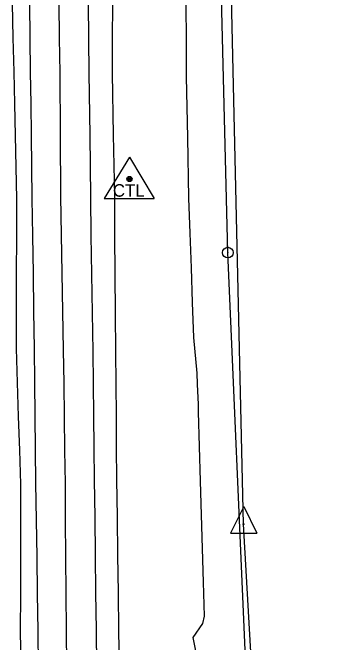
# Model space of a CAD drawing. Extents: x 1674300 to 1677920, y 225056 to 231852.
# Drawn here: x 1677429 to 1677555.5, y 229688.4 to 229939.8 of the extents above; entities that cross this region are included whole.
import ezdxf

# ---------------------------------------------------------------- set-up
doc = ezdxf.new("R2010")
doc.units = 0
for name, color, linetype in [('S_DITCHLINE', 7, 'Continuous'), ('S_EDGE_PAVEMENT', 7, 'Continuous'), ('S_ELECTRIC_UTILITIES', 7, 'Continuous'), ('S_EXIST_ROW', 7, 'Continuous'), ('S_PAVEMENT_CROWN', 7, 'Continuous'), ('S_PRIMARY_CTL', 7, 'Continuous'), ('S_SHOULDER', 7, 'Continuous'), ('S_UTILITY_POLE', 7, 'Continuous'), ('S_UTL_PT_SYM', 7, 'Continuous')]:
    doc.layers.add(name, color=color, linetype=linetype)

msp = doc.modelspace()

# ---------------------------------------------------------------- linework, layer by layer
at = {"layer": 'S_DITCHLINE'}
msp.add_lwpolyline([(1677504.24, 229674.27), (1677501.06, 229690.37), (1677504.91, 229695.99), (1677505.67, 229698.92), (1677505.25, 229712.38), (1677504.83, 229725.85), (1677504.41, 229739.31), (1677503.99, 229752.78), (1677503.62, 229766.63), (1677503.26, 229780.47), (1677503.28, 229783.38), (1677502.86, 229791.52), (1677502.67, 229795.84), (1677501.35, 229810.13), (1677500.87, 229824.02), (1677500.39, 229837.9), (1677499.91, 229851.79), (1677499.43, 229865.68), (1677498.96, 229889.9), (1677498.48, 229914.12), (1677498.4, 229928.6), (1677498.32, 229943.07)], dxfattribs=at)
at = {"layer": 'S_EDGE_PAVEMENT'}
for points in [[(1677439.31, 229678.67), (1677439.15, 229693.05), (1677438.94, 229707.77), (1677438.74, 229722.49), (1677438.53, 229737.21), (1677438.32, 229751.94), (1677438.17, 229765.36), (1677438.02, 229778.79), (1677437.87, 229792.22), (1677437.72, 229805.65), (1677437.49, 229820.65), (1677437.27, 229835.66), (1677437.04, 229850.66), (1677436.82, 229865.66), (1677436.66, 229878.26), (1677436.51, 229890.86), (1677436.35, 229903.45), (1677436.19, 229916.05), (1677436.02, 229929.77), (1677435.84, 229943.49)], [(1677462.69, 229678.82), (1677462.49, 229693.25), (1677462.29, 229708.26), (1677462.1, 229723.27), (1677461.9, 229738.28), (1677461.71, 229753.29), (1677461.57, 229766.11), (1677461.43, 229778.93), (1677461.29, 229791.75), (1677461.15, 229804.57), (1677460.91, 229819.98), (1677460.67, 229835.38), (1677460.43, 229850.78), (1677460.2, 229866.19), (1677459.91, 229890.83), (1677459.61, 229915.48), (1677459.47, 229929.46), (1677459.32, 229943.44)]]:
    msp.add_lwpolyline(points, dxfattribs=at)
at = {"layer": 'S_ELECTRIC_UTILITIES'}
for p, q in [((1677514.95, 229844), (1677508.13, 230120.1)), ((1677525.77, 229595.69), (1677514.95, 229844))]:
    msp.add_line(p, q, dxfattribs=at)
at = {"layer": 'S_EXIST_ROW'}
for p, q in [((1677521.25, 229735.57), (1677507.28, 230335.43)), ((1677521.27, 229742.66), (1677515.98, 229732.03)), ((1677521.27, 229742.66), (1677526.5, 229732.03)), ((1677521.25, 229735.57), (1677521.25, 229735.57)), ((1677555.5, 229117.02), (1677521.25, 229735.57)), ((1677515.98, 229732.03), (1677526.5, 229732.03))]:
    msp.add_line(p, q, dxfattribs=at)
for radius in [0.18, 0.09]:
    msp.add_circle((1677521.25, 229735.57), radius, dxfattribs=at)
at = {"layer": 'S_PAVEMENT_CROWN'}
msp.add_lwpolyline([(1677450.7, 229678.91), (1677450.55, 229693.34), (1677450.43, 229707.97), (1677450.3, 229722.61), (1677450.18, 229737.24), (1677450.05, 229751.88), (1677449.88, 229765.19), (1677449.7, 229778.5), (1677449.53, 229791.81), (1677449.35, 229805.12), (1677449.06, 229820.43), (1677448.77, 229835.75), (1677448.48, 229851.06), (1677448.19, 229866.38), (1677448.08, 229891.04), (1677447.97, 229915.7), (1677447.75, 229929.65), (1677447.52, 229943.6)], dxfattribs=at)
at = {"layer": 'S_PRIMARY_CTL'}
for p, q in [((1677475.64, 229882.09), (1677465.61, 229865.57)), ((1677475.64, 229882.09), (1677485.47, 229865.57)), ((1677465.61, 229865.57), (1677485.47, 229865.57))]:
    msp.add_line(p, q, dxfattribs=at)
for radius in [1.04, 0.609, 0.344]:
    msp.add_circle((1677475.64, 229873.39), radius, dxfattribs=at)
at = {"layer": 'S_SHOULDER'}
for points in [[(1677432.43, 229678.56), (1677432.2, 229693.05), (1677432.23, 229707.68), (1677432.26, 229722.31), (1677432.29, 229736.93), (1677432.31, 229751.56), (1677431.86, 229765.09), (1677431.41, 229778.62), (1677430.96, 229792.15), (1677430.51, 229805.69), (1677430.54, 229820.62), (1677430.58, 229835.55), (1677430.62, 229850.48), (1677430.65, 229865.41), (1677430.38, 229878.09), (1677430.11, 229890.77), (1677429.84, 229903.45), (1677429.57, 229916.13), (1677429.28, 229929.76), (1677428.99, 229943.4)], [(1677471.66, 229678.81), (1677471.46, 229693.07), (1677471.26, 229708.16), (1677471.06, 229723.25), (1677470.86, 229738.34), (1677470.65, 229753.43), (1677470.54, 229766.16), (1677470.43, 229778.89), (1677470.32, 229791.62), (1677470.2, 229804.35), (1677470.09, 229819.88), (1677469.98, 229835.41), (1677469.87, 229850.95), (1677469.75, 229866.48), (1677469.3, 229890.98), (1677468.85, 229915.48), (1677468.92, 229929.35), (1677468.98, 229943.22)]]:
    msp.add_lwpolyline(points, dxfattribs=at)
at = {"layer": 'S_UTILITY_POLE'}
msp.add_line((1677514.83, 229846.14), (1677514.83, 229848.25), dxfattribs=at)
msp.add_circle((1677514.95, 229844), 2.13, dxfattribs=at)
at = {"layer": 'S_UTL_PT_SYM'}
msp.add_lwpolyline([(1677514.95, 229844), (1677514.95, 229844.05), (1677514.95, 229844), (1677514.9, 229844), (1677514.95, 229844), (1677514.95, 229843.95), (1677514.95, 229844), (1677515, 229844)], dxfattribs=at)

# ---------------------------------------------------------------- texts
at = {"layer": 'S_PRIMARY_CTL'}
msp.add_text('CTL', height=5, rotation=360, dxfattribs=at).set_placement((1677469.06, 229866.31))

doc.saveas('drawing.dxf')
